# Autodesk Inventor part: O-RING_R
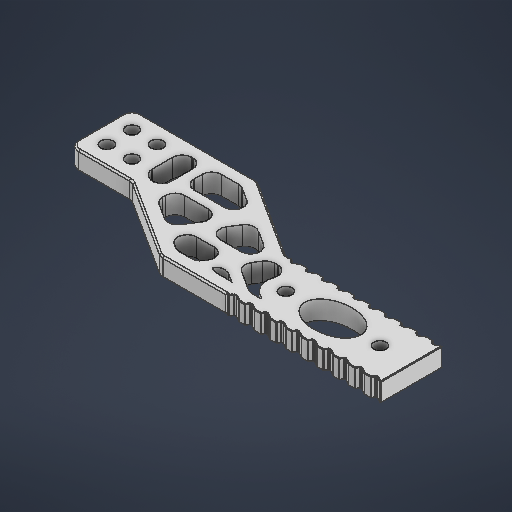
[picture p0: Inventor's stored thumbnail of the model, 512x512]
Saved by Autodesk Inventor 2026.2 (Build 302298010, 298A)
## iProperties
Created: 2026-05
Part Number: O-RING_R
Material: 일반
Document SubType Name: Modeling
Designer: work
Density: 1 g/cm^3
Appearance: 기본값
Author: work
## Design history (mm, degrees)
sketch "스케치1"
  geometry: L1 (0, 22)-(0, -22); L2 (0, -22)-(8, -22); L3 (8, -22)-(8, -30); L4 (8, -30)-(0, -30); L5 (0, -30)-(0, -22); L6 (0, -22)-(8, -30); L7 (8, -22)-(0, -30); L8 (-6, -36)-(14, -36); L9 (14, -36)-(14, -16); L10 (14, -16)-(-6, -16); L11 (-6, -16)-(-6, -36); L12 (-6, -36)-(14, -16); L13 (14, -36)-(-6, -16); L14 (-6, -16)-(-31, 0); L15 (-101, 0)-(-101, -20); L16 (-6, -36)-(-26, -36); L17 (-26, -36)-(-51, -20); L18 (0, 0)-(-31, 0); L19 (-101, -10)-(-15.375, -10); L20 (-101, 0)-(-99.268, -1); L21 (-99.268, -1)-(-98.577, -1); L22 (-98.577, -1)-(-98, 0); L23 (-93.577, -1)-(-93, 0); L24 (-94.268, -1)-(-93.577, -1); L25 (-96, 0)-(-94.268, -1); L26 (-88.577, -1)-(-88, 0); L27 (-89.268, -1)-(-88.577, -1); L28 (-91, 0)-(-89.268, -1); L29 (-83.577, -1)-(-83, 0); L30 (-84.268, -1)-(-83.577, -1); L31 (-86, 0)-(-84.268, -1); L32 (-78.577, -1)-(-78, 0); L33 (-79.268, -1)-(-78.577, -1); L34 (-81, 0)-(-79.268, -1); L35 (-73.577, -1)-(-73, 0); L36 (-74.268, -1)-(-73.577, -1); L37 (-76, 0)-(-74.268, -1); L38 (-68.577, -1)-(-68, 0); L39 (-69.268, -1)-(-68.577, -1); L40 (-71, 0)-(-69.268, -1); L41 (-63.577, -1)-(-63, 0); L42 (-64.268, -1)-(-63.577, -1); L43 (-66, 0)-(-64.268, -1); L44 (-58.577, -1)-(-58, 0); L45 (-59.268, -1)-(-58.577, -1); L46 (-61, 0)-(-59.268, -1); L47 (-53.577, -1)-(-53, 0); L48 (-54.268, -1)-(-53.577, -1); L49 (-56, 0)-(-54.268, -1); L50 (-73.577, -19)-(-73, -20); L51 (-74.268, -19)-(-73.577, -19); L52 (-76, -20)-(-74.268, -19); L53 (-78.577, -19)-(-78, -20); L54 (-79.268, -19)-(-78.577, -19); L55 (-81, -20)-(-79.268, -19); L56 (-83.577, -19)-(-83, -20); L57 (-84.268, -19)-(-83.577, -19); L58 (-86, -20)-(-84.268, -19); L59 (-71, -20)-(-69.268, -19); L60 (-69.268, -19)-(-68.577, -19); L61 (-68.577, -19)-(-68, -20); L62 (-66, -20)-(-64.268, -19); L63 (-64.268, -19)-(-63.577, -19); L64 (-63.577, -19)-(-63, -20)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; C1 r 2 at (-91, -10); C2 r 2 at (-61, -10); 48 further points; 1 other entity
  constraints: 194 end point, 39 symmetric about line, 38 horizontal alignment, 30 parallel, 26 point on line, 11 midpoint, 9 collinear, 9 horizontal, 8 perpendicular, 6 coincident, 4 vertical, 2 centre point, 17 other
  dimensions: "d0" = 44 distance of L1.start L1.end; "d1" = 8 distance of L3.end L4.end; "d2" = 8 distance of L2.end L3.end; "d3" = 6 distance between parallel lines of L2 L10; "d5" = 50 distance from line of L17.end L15; "d6" = 20 distance of L8.start L16.end; "d7" = 25 horizontal distance of L14.end L10.end; "d8" = 20 distance of L15.start L15.end; "d9" = 3 distance of L15.start L22.end; "d10" = 30 deg angle to the sketch x axis of L20; "d11" = 1 distance of the line from the sketch origin of L21; "d14" = 5 distance of L21.end L23.start; "d19" = 4 diameter of C1; "d20" = 4 diameter of C2; "d21" = 30 distance of C1.centre C2.centre; "d22" = 10 distance from line of L15 C1.centre; "d23" = 4 distance between parallel lines of L14 L80; "d24" = 4 distance between parallel lines of L16 L82; "d25" = 3 distance between parallel lines of L90 L86; "d26" = 3 distance between parallel lines of L91 L92; "d27" = 3 distance from line of point (-32.04, -15.735) L89; "d28" = 3 distance between parallel lines of L94 L93; "d29" = 3 distance between parallel lines of L87 L88; "d30" = 3 distance between parallel lines of L95 L96
  node "스케치 - 직사각형 패턴1" dims "d14" = 5, "d17" = 10
extrude "돌출1" new body sketch "스케치1" distance "d31" = 6; taper "d32" = 0 deg
hole "구멍1" sketch "스케치1" diameter "d33" = 4; stored, may be unused: countersink angle "d37" = 90 deg, drill point angle "d39" = 118 deg; dims "d34" = 6, "d35" = 6.2, "d36" = 3, "d38" = 8
sketch "스케치2"
  geometry: C1 r 2 at (61, -10) reference; C2 r 2 at (91, -10) reference; 3 further points
  constraints: 2 coincident
hole "구멍2" sketch "스케치2" at (61, -10), (91, -10) diameter "d40" = 4; stored, may be unused: countersink angle "d44" = 90 deg, drill point angle "d46" = 118 deg; dims "d41" = 6, "d42" = 6.2, "d43" = 3, "d45" = 8
fillet "모깎기1" dims "d47" = 3
fillet "모깎기2" dims "d48" = 0.2
sketch "스케치3"
  geometry: L1 (51.878, -20)-(52.378, -20); L2 (52.378, -20)-(52.378, -19.5); L3 (52.378, -19.5)-(51.878, -19.5); L4 (51.878, -19.5)-(51.878, -20); L5 (51.878, -0.5)-(52.378, -0.5); L6 (52.378, -0.5)-(52.378, 0); L7 (52.378, 0)-(51.878, 0); L8 (51.878, 0)-(51.878, -0.5); L9 (31.878, 0)-(52.885, 0) reference; L10 (52.378, -19.5)-(52.378, -0.5); A1 r 3 centre (51.878, -23) between (51.878, -20) and (50.261, -20.473) reference; 1 further point
  constraints: 18 end point, 4 parallel, 2 horizontal, 2 perpendicular, 1 point on line, 1 vertical
  dimensions: "d49" = 0.5 distance of L3.end L2.end; "d50" = 0.5 distance of L2.end L1.end; "d51" = 0.5 distance of L7.end L6.end; "d52" = 0.5 distance of L6.end L5.end
extrude "돌출2" cut sketch "스케치3" extent not by distance; stored distance "d53" = 0; taper "d54" = 0 deg
chamfer "모따기1" distance "d55" = 0.5; stored, may be unused: second distance "d56" = 2, angle "d57" = 45 deg
chamfer "모따기2" distance "d58" = 0.2; stored, may be unused: second distance "d59" = 2, angle "d60" = 45 deg
node "솔리드1"
feature "A9D066F2-1C7D-4E18-AEED-F7BC21143FA4" dims "d33" = 4, "d34" = 6, "d35" = 6.2, "d36" = 3, "d37" = 90 deg, "d38" = 8, "d39" = 118 deg
